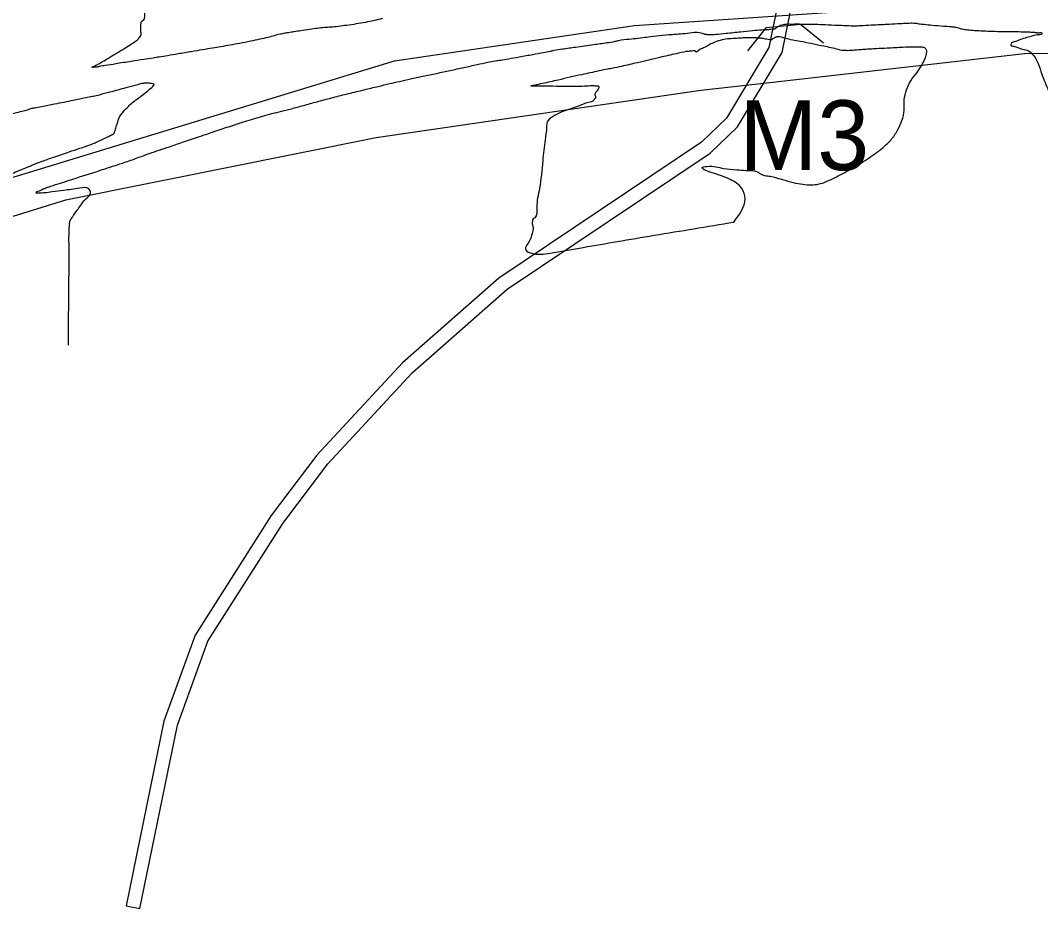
# Model space of a CAD drawing. Extents: x -478495 to -472450, y -1118050 to -1113745.
# Drawn here: x -477790.3 to -477644.2, y -1117531.6 to -1117404.3 of the extents above; entities that cross this region are included whole.
import ezdxf

# ---------------------------------------------------------------- set-up
doc = ezdxf.new("R2010")
doc.units = 0
for name, color, linetype in [('hranice kú', 7, 'Continuous'), ('ObPÚ', 7, 'Continuous'), ('silnice', 7, 'Continuous'), ('TP_MO', 7, 'Continuous'), ('vodní plochy', 7, 'Continuous'), ('Vrstevnice_vedlejsi', 7, 'Continuous')]:
    doc.layers.add(name, color=color, linetype=linetype)

msp = doc.modelspace()

# ---------------------------------------------------------------- linework, layer by layer
at = {"layer": 'hranice kú'}
for p, q in [((-477682.9789219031, -1117413.1964567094), (-477646.4839551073, -1117409.042558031)), ((-477646.4839551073, -1117409.042558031), (-477622.5324247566, -1117408.7864354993)), ((-477692.82839548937, -1117414.3175349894), (-477682.9789219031, -1117413.1964567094)), ((-477739.35326084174, -1117421.059193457), (-477692.82839548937, -1117414.3175349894)), ((-477761.4579358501, -1117425.5097991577), (-477739.35326084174, -1117421.059193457)), ((-477766.4499313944, -1117426.5148989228), (-477761.4579358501, -1117425.5097991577)), ((-477771.4419269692, -1117427.5199987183), (-477766.4499313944, -1117426.5148989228)), ((-477783.82000912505, -1117430.012230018), (-477771.4419269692, -1117427.5199987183)), ((-477792.76052931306, -1117432.7791217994), (-477783.82000912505, -1117430.012230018))]:
    msp.add_line(p, q, dxfattribs=at)
at = {"layer": 'ObPÚ'}
for p, q in [((-477682.9789219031, -1117413.1964567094), (-477646.4839551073, -1117409.042558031)), ((-477646.4839551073, -1117409.042558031), (-477622.5324247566, -1117408.7864354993)), ((-477692.82839548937, -1117414.3175349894), (-477682.9789219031, -1117413.1964567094)), ((-477739.35326084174, -1117421.059193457), (-477692.82839548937, -1117414.3175349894)), ((-477761.4579358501, -1117425.5097991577), (-477739.35326084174, -1117421.059193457)), ((-477766.4499313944, -1117426.5148989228), (-477761.4579358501, -1117425.5097991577)), ((-477771.4419269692, -1117427.5199987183), (-477766.4499313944, -1117426.5148989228)), ((-477783.82000912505, -1117430.012230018), (-477771.4419269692, -1117427.5199987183)), ((-477792.76052931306, -1117432.7791217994), (-477783.82000912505, -1117430.012230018))]:
    msp.add_line(p, q, dxfattribs=at)
at = {"layer": 'silnice'}
msp.add_lwpolyline([(-478070.49536841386, -1117514.1125956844), (-478065.5203558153, -1117512.4650769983), (-477835.70100830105, -1117440.2943423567), (-477736.72771266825, -1117410.083337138), (-477702.33868620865, -1117405.048169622), (-477652.85203839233, -1117401.6913912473), (-477590.7840394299, -1117403.36978045), (-477332.44696264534, -1117414.2793100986), (-477204.95593777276, -1117416.7968938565), (-477142.0491820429, -1117416.7968938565), (-477096.7563179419, -1117410.083337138), (-477037.20458922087, -1117399.1738074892), (-476978.49161720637, -1117379.0331373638), (-476883.71210528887, -1117344.6261592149), (-476756.22108038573, -1117298.470456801), (-476633.76259959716, -1117254.8324505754), (-476588.4697354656, -1117242.244531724), (-476550.72568205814, -1117234.6917804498), (-476503.7553044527, -1117230.4958074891), (-476424.07341389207, -1117228.8174183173)], dxfattribs=at)
at = {"layer": 'TP_MO'}
for p, q in [((-477686.1335073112, -1117408.6427197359), (-477683.4436932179, -1117405.3322838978)), ((-477683.4436932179, -1117405.3322838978), (-477678.58482577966, -1117404.8267134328)), ((-477678.58482577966, -1117404.8267134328), (-477675.27110085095, -1117407.5124744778))]:
    msp.add_line(p, q, dxfattribs=at)
at = {"layer": 'vodní plochy'}
msp.add_line((-477775.14882216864, -1117531.1861287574), (-477773.18917783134, -1117531.5858712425), dxfattribs=at)
msp.add_line((-477775.14882216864, -1117531.1861287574), (-477773.18917783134, -1117531.5858712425), dxfattribs=at)
msp.add_line((-477775.14882216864, -1117531.1861287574), (-477773.18917783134, -1117531.5858712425), dxfattribs=at)
for points in [[(-477773.18917783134, -1117531.5858712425), (-477767.82195687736, -1117505.2743220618), (-477763.4553336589, -1117493.2688194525), (-477752.74284957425, -1117476.373803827), (-477746.29490719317, -1117467.8684294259), (-477734.18431302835, -1117454.7962666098), (-477720.57264214, -1117442.8340134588), (-477691.49460304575, -1117423.3092294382), (-477687.59878295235, -1117419.5572742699), (-477681.21515979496, -1117408.9192692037), (-477679.53718695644, -1117400.6535460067), (-477679.8030720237, -1117385.9063838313), (-477676.91768370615, -1117377.2443680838), (-477671.55484817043, -1117365.9807198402), (-477667.46817764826, -1117356.7105103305), (-477665.007, -1117343.8538548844), (-477665.007, -1117334.2139405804), (-477668.28156019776, -1117321.1106292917), (-477683.57738190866, -1117282.1860568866)], [(-477773.18917783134, -1117531.5858712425), (-477767.82195687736, -1117505.2743220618), (-477763.4553336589, -1117493.2688194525), (-477752.74284957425, -1117476.373803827), (-477746.29490719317, -1117467.8684294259), (-477734.18431302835, -1117454.7962666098), (-477720.57264214, -1117442.8340134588), (-477691.49460304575, -1117423.3092294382), (-477687.59878295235, -1117419.5572742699), (-477681.21515979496, -1117408.9192692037), (-477679.53718695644, -1117400.6535460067), (-477679.8030720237, -1117385.9063838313), (-477676.91768370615, -1117377.2443680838), (-477671.55484817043, -1117365.9807198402), (-477667.46817764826, -1117356.7105103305), (-477665.007, -1117343.8538548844), (-477665.007, -1117334.2139405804), (-477668.28156019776, -1117321.1106292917), (-477683.57738190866, -1117282.1860568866)], [(-477667.007, -1117334.4600594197), (-477667.007, -1117343.6641451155), (-477669.38982235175, -1117356.1114896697), (-477673.3731518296, -1117365.1472801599), (-477678.77631629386, -1117376.4956319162), (-477681.8089279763, -1117385.5996161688), (-477681.5408130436, -1117400.4704539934), (-477683.1068402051, -1117408.1847307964), (-477689.17721704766, -1117418.3007257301), (-477692.75539695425, -1117421.746770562), (-477721.79535786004, -1117441.2459865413), (-477735.58168697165, -1117453.3617333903), (-477747.82909280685, -1117466.581570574), (-477754.38715042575, -1117475.232196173), (-477765.2606663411, -1117492.3811805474), (-477769.75204312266, -1117504.7296779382), (-477775.14882216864, -1117531.1861287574)], [(-477681.5408130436, -1117400.4704539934), (-477683.1068402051, -1117408.1847307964), (-477689.17721704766, -1117418.3007257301), (-477692.75539695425, -1117421.746770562), (-477721.79535786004, -1117441.2459865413), (-477735.58168697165, -1117453.3617333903), (-477747.82909280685, -1117466.581570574), (-477754.38715042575, -1117475.232196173), (-477765.2606663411, -1117492.3811805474), (-477769.75204312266, -1117504.7296779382), (-477775.14882216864, -1117531.1861287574)]]:
    msp.add_lwpolyline(points, dxfattribs=at)
at = {"layer": 'Vrstevnice_vedlejsi'}
for points in [[(-477738.43700000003, -1117404.029), (-477739.64400000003, -1117404.317), (-477740.902, -1117404.5760000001), (-477742.212, -1117404.807), (-477743.574, -1117405.008), (-477744.784, -1117405.163), (-477745.843, -1117405.272), (-477746.75, -1117405.335), (-477747.765, -1117405.44), (-477748.889, -1117405.588), (-477750.12200000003, -1117405.779), (-477751.125, -1117405.935), (-477751.89900000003, -1117406.057), (-477752.443, -1117406.144), (-477753.121, -1117406.287), (-477753.93200000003, -1117406.486), (-477754.876, -1117406.74), (-477756.014, -1117407.008), (-477757.34500000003, -1117407.29), (-477758.869, -1117407.5860000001), (-477760.282, -1117407.848), (-477761.586, -1117408.0760000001), (-477762.77900000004, -1117408.271), (-477764.195, -1117408.506), (-477765.833, -1117408.7820000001), (-477767.693, -1117409.1), (-477769.227, -1117409.357), (-477770.435, -1117409.552), (-477771.317, -1117409.687), (-477772.64900000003, -1117409.894), (-477774.43200000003, -1117410.176), (-477776.667, -1117410.531), (-477778.181, -1117410.775), (-477778.976, -1117410.906), (-477779.05100000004, -1117410.926), (-477779.226, -1117410.956), (-477779.5, -1117410.994), (-477779.875, -1117411.041), (-477780.06, -1117411.041), (-477780.055, -1117410.994), (-477779.86, -1117410.9), (-477779.63800000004, -1117410.7920000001), (-477779.387, -1117410.669), (-477779.109, -1117410.5320000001), (-477778.54000000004, -1117410.207), (-477777.68, -1117409.6940000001), (-477776.52900000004, -1117408.994), (-477775.501, -1117408.359), (-477774.593, -1117407.79), (-477773.808, -1117407.287), (-477773.289, -1117406.801), (-477773.038, -1117406.331), (-477773.053, -1117405.877), (-477773.061, -1117405.472), (-477773.06, -1117405.117), (-477773.052, -1117404.81), (-477772.996, -1117404.5690000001), (-477772.893, -1117404.395), (-477772.742, -1117404.287), (-477772.50800000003, -1117403.024), (-477772.191, -1117400.605), (-477771.79000000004, -1117397.031), (-477771.568, -1117390.931), (-477771.525, -1117382.305), (-477771.66000000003, -1117371.152), (-477771.923, -1117360.756), (-477772.313, -1117351.115), (-477772.829, -1117342.231), (-477773.795, -1117334.825), (-477775.208, -1117328.897), (-477777.071, -1117324.449), (-477778.387, -1117319.217), (-477779.156, -1117313.2010000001), (-477779.379, -1117306.402), (-477780.166, -1117299.691), (-477781.516, -1117293.068), (-477783.429, -1117286.534), (-477785.561, -1117281.406), (-477787.912, -1117277.6840000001), (-477790.482, -1117275.368), (-477792.967, -1117272.524), (-477795.368, -1117269.152), (-477797.684, -1117265.251), (-477800.572, -1117260.279), (-477804.033, -1117254.234), (-477808.066, -1117247.117), (-477810.645, -1117241.138), (-477811.77, -1117236.296), (-477811.44, -1117232.593), (-477811.873, -1117226.914), (-477813.068, -1117219.259), (-477815.026, -1117209.6300000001), (-477818.88800000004, -1117199.125), (-477824.655, -1117187.744), (-477832.32800000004, -1117175.4880000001), (-477837.806, -1117166.958), (-477841.092, -1117162.155)], [(-477714.4, -1117408.695), (-477713.88, -1117408.578), (-477712.673, -1117408.383), (-477710.778, -1117408.11), (-477708.197, -1117407.759), (-477706.31200000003, -1117407.486), (-477705.124, -1117407.291), (-477704.632, -1117407.174), (-477703.11, -1117406.969), (-477700.556, -1117406.677), (-477696.971, -1117406.297), (-477694.461, -1117406.081), (-477693.026, -1117406.03), (-477692.66500000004, -1117406.142), (-477692.424, -1117406.219), (-477692.302, -1117406.259), (-477692.3, -1117406.263), (-477692.18700000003, -1117406.278), (-477691.963, -1117406.303), (-477691.628, -1117406.339), (-477690.71400000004, -1117406.286), (-477689.219, -1117406.145), (-477687.14400000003, -1117405.916), (-477685.43700000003, -1117405.745), (-477684.098, -1117405.632), (-477683.125, -1117405.577), (-477682.45, -1117405.507), (-477682.072, -1117405.423), (-477681.99, -1117405.325), (-477681.825, -1117405.2110000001), (-477681.575, -1117405.081), (-477681.24, -1117404.935), (-477680.853, -1117404.842), (-477680.414, -1117404.802), (-477679.923, -1117404.814), (-477679.548, -1117404.813), (-477679.29000000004, -1117404.8), (-477679.14900000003, -1117404.774), (-477679.01300000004, -1117404.7650000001), (-477678.88300000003, -1117404.774), (-477678.757, -1117404.801), (-477678.434, -1117404.8190000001), (-477677.91500000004, -1117404.828), (-477677.19800000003, -1117404.829), (-477676.088, -1117404.858), (-477674.58400000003, -1117404.915), (-477672.688, -1117405), (-477671.36100000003, -1117405.051), (-477670.605, -1117405.0690000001)], [(-477670.605, -1117405.0690000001), (-477670.42, -1117405.054), (-477669.569, -1117405.008), (-477668.052, -1117404.93), (-477665.87, -1117404.82), (-477664.26300000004, -1117404.739), (-477663.229, -1117404.687), (-477662.77, -1117404.664), (-477662.351, -1117404.67), (-477661.971, -1117404.705), (-477661.63, -1117404.769), (-477660.869, -1117404.857), (-477659.688, -1117404.968), (-477658.087, -1117405.1030000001), (-477657.02, -1117405.192), (-477656.48600000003, -1117405.237), (-477656.485, -1117405.237), (-477656.304, -1117405.284), (-477655.941, -1117405.377), (-477655.397, -1117405.516), (-477654.626, -1117405.633), (-477653.628, -1117405.726), (-477652.401, -1117405.796), (-477651.07800000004, -1117405.847), (-477649.657, -1117405.8800000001), (-477648.14, -1117405.894), (-477646.935, -1117405.914), (-477646.043, -1117405.939), (-477645.46400000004, -1117405.97), (-477644.928, -1117406.009), (-477644.435, -1117406.058), (-477643.985, -1117406.115), (-477643.977, -1117406.213), (-477644.411, -1117406.352), (-477645.287, -1117406.531), (-477646.167, -1117406.761), (-477647.052, -1117407.044), (-477647.941, -1117407.379), (-477648.398, -1117407.649), (-477648.423, -1117407.855), (-477648.014, -1117407.997), (-477647.457, -1117408.181), (-477646.749, -1117408.406), (-477645.891, -1117408.674), (-477645.146, -1117409.362), (-477644.514, -1117410.473), (-477643.994, -1117412.004), (-477643.021, -1117414.3900000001), (-477641.596, -1117417.631), (-477637.841, -1117425.821)], [(-477688.123, -1117433.202), (-477686.515, -1117429.862), (-477686.949, -1117428.387), (-477688.62200000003, -1117427.107), (-477691.532, -1117426.022), (-477692.655, -1117425.393), (-477691.99100000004, -1117425.222), (-477689.539, -1117425.508), (-477687.673, -1117425.698), (-477686.393, -1117425.793), (-477685.699, -1117425.7920000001), (-477685.119, -1117425.872), (-477684.653, -1117426.034), (-477684.3, -1117426.276), (-477683.922, -1117426.453), (-477683.517, -1117426.562), (-477683.086, -1117426.605), (-477682.29000000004, -1117426.781), (-477681.131, -1117427.09), (-477679.607, -1117427.5320000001), (-477678.229, -1117427.788), (-477676.995, -1117427.857), (-477675.907, -1117427.741), (-477674.26, -1117427.121), (-477672.055, -1117425.9980000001), (-477669.292, -1117424.371), (-477667.14, -1117422.837), (-477665.597, -1117421.396), (-477664.66500000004, -1117420.047), (-477664.037, -1117418.642), (-477663.712, -1117417.18), (-477663.691, -1117415.663), (-477663.37700000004, -1117414.253), (-477662.77, -1117412.9510000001), (-477661.87, -1117411.756), (-477661.194, -1117410.712), (-477660.742, -1117409.818), (-477660.514, -1117409.074), (-477660.521, -1117408.548), (-477660.76300000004, -1117408.24), (-477661.242, -1117408.149), (-477662.29600000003, -1117408.126), (-477663.927, -1117408.171), (-477666.13300000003, -1117408.283), (-477667.669, -1117408.361), (-477668.53500000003, -1117408.405), (-477668.73, -1117408.414), (-477669.161, -1117408.445), (-477669.829, -1117408.497), (-477670.734, -1117408.57), (-477671.397, -1117408.615), (-477671.819, -1117408.634), (-477671.999, -1117408.626), (-477672.142, -1117408.621), (-477672.248, -1117408.618), (-477672.316, -1117408.618), (-477673.39900000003, -1117408.398), (-477675.49700000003, -1117407.957), (-477678.61, -1117407.297), (-477680.733, -1117406.865), (-477681.86600000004, -1117406.663), (-477682.009, -1117406.69), (-477682.156, -1117406.735), (-477682.305, -1117406.8), (-477682.456, -1117406.883), (-477682.571, -1117406.955), (-477682.64900000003, -1117407.014), (-477682.69, -1117407.061), (-477682.718, -1117407.092), (-477682.731, -1117407.108), (-477682.732, -1117407.108), (-477682.95900000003, -1117407.07), (-477683.412, -1117406.995), (-477684.092, -1117406.883), (-477684.811, -1117406.813), (-477685.567, -1117406.784), (-477686.362, -1117406.796), (-477687.244, -1117406.835), (-477688.211, -1117406.9), (-477689.265, -1117406.991), (-477690.32300000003, -1117407.246), (-477691.387, -1117407.666), (-477692.456, -1117408.25), (-477693.178, -1117408.625), (-477693.552, -1117408.7920000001), (-477693.57800000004, -1117408.749), (-477693.615, -1117408.715), (-477693.662, -1117408.688), (-477693.72000000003, -1117408.67), (-477693.951, -1117408.679), (-477694.354, -1117408.713), (-477694.93, -1117408.774), (-477696.381, -1117409.0690000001), (-477698.707, -1117409.598), (-477701.907, -1117410.36), (-477704.195, -1117410.889), (-477705.572, -1117411.185)], [(-477783.4189451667, -1117450.8237259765), (-477783.385, -1117443.847), (-477783.344, -1117437.193), (-477783.30700000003, -1117433.697), (-477783.275, -1117433.361), (-477783.245, -1117433.129), (-477783.218, -1117433.001), (-477783.192, -1117432.977), (-477783.169, -1117432.9510000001), (-477783.147, -1117432.922), (-477783.12700000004, -1117432.8900000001), (-477783.109, -1117432.856), (-477783.092, -1117432.82), (-477783.076, -1117432.783), (-477782.922, -1117432.552), (-477782.631, -1117432.129), (-477782.201, -1117431.512), (-477781.664, -1117430.783), (-477781.01900000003, -1117429.941), (-477780.266, -1117428.987), (-477780.53, -1117428.456), (-477781.81, -1117428.35), (-477784.107, -1117428.6670000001), (-477785.776, -1117428.888), (-477786.815, -1117429.013), (-477787.226, -1117429.04), (-477787.571, -1117429.053), (-477787.848, -1117429.051), (-477788.059, -1117429.033), (-477788.02900000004, -1117428.9440000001), (-477787.757, -1117428.7820000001), (-477787.246, -1117428.548), (-477786.835, -1117428.368), (-477786.525, -1117428.243), (-477786.317, -1117428.173), (-477784.916, -1117427.7210000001), (-477782.322, -1117426.887), (-477778.536, -1117425.672), (-477775.697, -1117424.742), (-477773.80700000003, -1117424.097), (-477772.864, -1117423.7380000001), (-477771.744, -1117423.335), (-477770.44800000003, -1117422.886), (-477768.974, -1117422.392), (-477767.09500000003, -1117421.76), (-477764.81, -1117420.99), (-477762.118, -1117420.08), (-477759.905, -1117419.343), (-477758.17, -1117418.777), (-477756.914, -1117418.384), (-477755.618, -1117418.008), (-477754.281, -1117417.651), (-477752.90400000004, -1117417.311), (-477751.327, -1117416.903), (-477749.55, -1117416.426), (-477747.572, -1117415.881), (-477745.496, -1117415.333), (-477743.321, -1117414.7820000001), (-477741.048, -1117414.229), (-477739.07300000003, -1117413.753), (-477737.397, -1117413.355), (-477736.01900000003, -1117413.035), (-477734.443, -1117412.6840000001), (-477732.669, -1117412.301), (-477730.696, -1117411.887), (-477728.742, -1117411.469), (-477726.80700000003, -1117411.047), (-477724.891, -1117410.622), (-477723.376, -1117410.303), (-477722.261, -1117410.09), (-477721.548, -1117409.983), (-477720.41500000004, -1117409.793), (-477718.862, -1117409.521), (-477716.891, -1117409.1670000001), (-477715.40400000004, -1117408.891), (-477714.4, -1117408.695)], [(-477705.572, -1117411.185), (-477706.038, -1117411.2480000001), (-477707.477, -1117411.545), (-477709.889, -1117412.075), (-477713.27400000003, -1117412.839), (-477715.534, -1117413.349), (-477716.668, -1117413.604), (-477716.67600000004, -1117413.606), (-477716.75, -1117413.617), (-477716.89, -1117413.638), (-477717.096, -1117413.669), (-477717.175, -1117413.687), (-477717.126, -1117413.691), (-477716.95, -1117413.682), (-477716.808, -1117413.675), (-477716.7, -1117413.668), (-477716.626, -1117413.663), (-477715.907, -1117413.669), (-477714.541, -1117413.685), (-477712.53, -1117413.712), (-477710.84500000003, -1117413.713), (-477709.48600000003, -1117413.686), (-477708.454, -1117413.633), (-477707.773, -1117413.662), (-477707.444, -1117413.774), (-477707.467, -1117413.968), (-477707.548, -1117414.166), (-477707.68700000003, -1117414.367), (-477707.884, -1117414.573), (-477707.993, -1117414.774), (-477708.012, -1117414.9710000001), (-477707.943, -1117415.164), (-477707.91500000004, -1117415.314), (-477707.929, -1117415.421), (-477707.985, -1117415.486), (-477708.043, -1117415.56), (-477708.103, -1117415.644), (-477708.166, -1117415.7380000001), (-477708.933, -1117416.051), (-477710.403, -1117416.584), (-477712.577, -1117417.335), (-477714.059, -1117418.09), (-477714.848, -1117418.847), (-477714.944, -1117419.608), (-477715.161, -1117421.452), (-477715.5, -1117424.382), (-477715.95900000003, -1117428.397), (-477716.33900000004, -1117431.126), (-477716.641, -1117432.572), (-477716.863, -1117432.733), (-477716.978, -1117433.03), (-477716.984, -1117433.465), (-477716.882, -1117434.036), (-477717.01300000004, -1117434.837), (-477717.376, -1117435.868), (-477717.971, -1117437.128), (-477716.886, -1117437.707), (-477714.12200000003, -1117437.606), (-477709.678, -1117436.825), (-477704.814, -1117435.9880000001), (-477699.53, -1117435.0960000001), (-477688.123, -1117433.202)], [(-477824.901, -1117439.31), (-477824.387, -1117439.092), (-477823.13800000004, -1117438.597), (-477821.155, -1117437.828), (-477818.43700000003, -1117436.783), (-477816.34, -1117435.969), (-477814.865, -1117435.386), (-477814.012, -1117435.034), (-477813.235, -1117434.715), (-477812.53500000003, -1117434.43), (-477811.911, -1117434.178), (-477810.759, -1117433.6570000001), (-477809.079, -1117432.868), (-477806.87200000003, -1117431.81), (-477804.903, -1117430.911), (-477803.172, -1117430.171), (-477801.681, -1117429.591), (-477800.47000000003, -1117429.18), (-477799.54000000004, -1117428.938), (-477798.891, -1117428.866), (-477797.518, -1117428.458), (-477795.42, -1117427.716), (-477792.599, -1117426.639), (-477790.49100000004, -1117425.817), (-477789.09500000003, -1117425.25), (-477788.413, -1117424.938), (-477787.221, -1117424.482), (-477785.51900000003, -1117423.8800000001), (-477783.308, -1117423.134), (-477781.799, -1117422.626), (-477780.995, -1117422.356), (-477780.893, -1117422.323), (-477780.673, -1117422.243), (-477780.33400000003, -1117422.116), (-477779.87700000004, -1117421.942), (-477779.306, -1117421.697), (-477778.62200000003, -1117421.381), (-477777.825, -1117420.995), (-477777.273, -1117420.714), (-477776.968, -1117420.541), (-477776.908, -1117420.473), (-477776.761, -1117420.085), (-477776.528, -1117419.374), (-477776.208, -1117418.342), (-477775.433, -1117417.229), (-477774.20300000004, -1117416.037), (-477772.518, -1117414.766), (-477771.50800000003, -1117413.892), (-477771.173, -1117413.4170000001), (-477771.514, -1117413.341), (-477771.825, -1117413.296), (-477772.107, -1117413.281), (-477772.359, -1117413.298), (-477772.554, -1117413.314), (-477772.693, -1117413.328), (-477772.775, -1117413.34), (-477772.837, -1117413.35), (-477772.88, -1117413.356), (-477772.902, -1117413.36), (-477773.677, -1117413.566), (-477775.204, -1117413.974), (-477777.485, -1117414.585), (-477779.042, -1117414.997), (-477779.876, -1117415.21), (-477779.988, -1117415.224), (-477780.954, -1117415.411), (-477782.776, -1117415.772), (-477785.454, -1117416.307), (-477787.28, -1117416.6670000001), (-477788.255, -1117416.851), (-477788.379, -1117416.861), (-477788.576, -1117416.905), (-477788.848, -1117416.983), (-477789.192, -1117417.0960000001), (-477789.875, -1117417.287), (-477790.896, -1117417.555), (-477792.255, -1117417.901), (-477793.223, -1117418.177), (-477793.80100000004, -1117418.384), (-477793.988, -1117418.52), (-477794.441, -1117418.674), (-477795.159, -1117418.845), (-477796.142, -1117419.033), (-477797.208, -1117419.25), (-477798.354, -1117419.496), (-477799.582, -1117419.771), (-477800.586, -1117419.99), (-477801.364, -1117420.153), (-477801.918, -1117420.26), (-477802.397, -1117420.33), (-477802.804, -1117420.365), (-477803.136, -1117420.3630000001), (-477803.451, -1117420.298), (-477803.75, -1117420.17), (-477804.032, -1117419.979), (-477804.244, -1117419.751), (-477804.386, -1117419.4880000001)]]:
    msp.add_spline(points, degree=3, dxfattribs=at)

# ---------------------------------------------------------------- texts
at = {"layer": 'TP_MO'}
msp.add_text('M3', height=9.999999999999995, rotation=359.99999385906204, dxfattribs=at).set_placement((-477687.30275116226, -1117425.7508867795))

doc.saveas('drawing.dxf')
